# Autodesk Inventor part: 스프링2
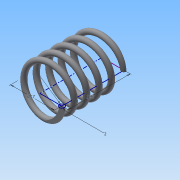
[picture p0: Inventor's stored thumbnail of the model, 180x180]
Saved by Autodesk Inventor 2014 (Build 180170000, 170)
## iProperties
Created: 2016-01
Part Number: 스프링2
Material: 강철, 탄소
Document SubType Name: Modeling
Designer: Administrator
Density: 8.08 g/cm^3
Appearance: 반연마
Mass: 6.63924 g
Surface Area: 16.7182 cm^2
Volume: 0.821689 cm^3
Author: Administrator
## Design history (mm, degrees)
sketch "스케치1"
  geometry: L1 (0, 0)-(8.5, 0); L2 (8.5, 0)-(8.5, 20.5); L3 (8.5, 20.5)-(0, 20.5); L4 (0, 20.5)-(0, 0); C1 r 1 at (8.5, 0)
  constraints: 8 end point, 2 parallel, 1 centre point, 1 coincident, 1 horizontal, 1 perpendicular
  dimensions: "d0" = 2 diameter of C1; "d1" = 17 diameter of L2 L4; "d2" = 20.5 distance of L1.end L2.end (derived)
feature "코일1" sketch "스케치1" pitch "d3" = 10; turns "d5" = 5; dims "d4" = 20.5 (= d2), "d6" = 0, angle "d7" = 90 deg, angle "d8" = 90 deg, "d9" = 0, "d10" = 0
node "작업 평면1"
sketch "스케치2"
  geometry: L1 (-9.5, 0)-(-7.5, 0) reference; L2 (-9.5, 0)-(-7.5, 0) reference; 1 further point
  constraints: 2 horizontal alignment
extrude "돌출1" cut sketch "스케치2" stored distance "d12" = 10; taper "d13" = 0 deg
node "작업 평면2"
sketch "스케치3"
  geometry: L1 (-7.5, 0)-(-9.5, 0) reference; 1 further point
  constraints: 1 horizontal alignment
extrude "돌출2" cut sketch "스케치3" stored distance "d15" = 10; taper "d16" = 0 deg
node "솔리드1"
node "절단 모서리 투영1"
node "절단 모서리 투영2"
node "절단 모서리 투영3"
other parameters: "d11" = 0, "d14" = 20.5 (= d2)
